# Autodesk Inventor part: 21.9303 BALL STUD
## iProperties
Created: 2012-05
Part Number: 21.9303 BALL STUD
Document SubType Name: Modeling
Designer: Administrator
Density: 7.85 g/cm^3
Material: Steel
Mass: 9.93676 g
Surface Area: 9.59563 cm^2
Volume: 1.26583 cm^3
Author: Administrator
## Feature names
1. Base1
2. Extrusion1
3. Chamfer1
4. Extrusion2
